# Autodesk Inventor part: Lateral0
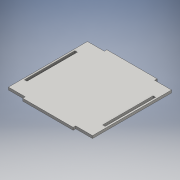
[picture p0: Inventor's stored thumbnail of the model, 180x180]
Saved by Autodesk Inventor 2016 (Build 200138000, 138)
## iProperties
Created: 2016-06
Part Number: Lateral0
Material: Genérico
Document SubType Name: Modeling
Designer: adm
Density: 1 g/cm^3
Appearance: Valor por defecto
Author: adm
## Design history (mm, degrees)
sketch "Boceto1"
  geometry: L1 (-30, -50)-(30, -50); L2 (50, -47)-(50, 47); L3 (30, 50)-(-30, 50); L4 (-50, 47)-(-50, -47); L5 (-50, -50)-(50, 50); L6 (50, -50)-(-50, 50); L7 (48, 30)-(48, -30); L8 (-48, -30)-(-48, 30); L9 (-45, 30)-(-45, -30); L10 (45, -30)-(45, 30); L11 (-48, -30)-(-45, -30); L12 (-48, 30)-(-45, 30); L13 (45, 30)-(48, 30); L14 (45, -30)-(48, -30); L15 (-50, 47)-(-30, 47); L16 (30, 47)-(50, 47); L17 (50, -47)-(30, -47); L18 (-30, -47)-(-50, -47); L19 (30, 50)-(30, 47); L20 (30, -47)-(30, -50); L21 (-30, 50)-(-30, 47); L22 (-30, -47)-(-30, -50); 1 further point
  constraints: 44 end point, 8 parallel, 2 midpoint, 1 horizontal, 1 perpendicular
  dimensions: "d0" = 100 distance of L6.end L5.end; "d1" = 100 distance of L5.end L6.start
extrude "Extrusión1" new body sketch "Boceto1" distance "d11" = 3; taper "d12" = 0 deg
node "Sólido1"
other parameters: "d8" = 3
